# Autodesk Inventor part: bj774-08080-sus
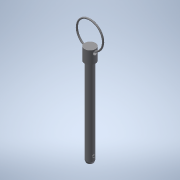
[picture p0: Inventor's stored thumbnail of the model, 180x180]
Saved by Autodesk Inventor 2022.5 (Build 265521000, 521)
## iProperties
Created: 2016-12
Part Number: bj774-08080-sus
Material: 一般
Document SubType Name: Modeling
Designer: imaocorp
Density: 1 g/cm^3
Appearance: 既定
Author: imaocorp
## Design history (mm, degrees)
node "bj774-08080-sus.x_t1"
node "bj774-08080-sus"
node "Base1"
